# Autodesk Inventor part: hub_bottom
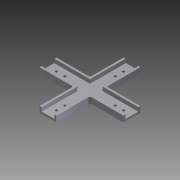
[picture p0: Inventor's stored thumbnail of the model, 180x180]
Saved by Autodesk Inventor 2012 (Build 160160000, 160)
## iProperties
Created: 2011-06
Part Number: hub_bottom
Document SubType Name: Modeling
Designer: Bruce
Density: 1 g/cm^3
Material: Default
Author: Bruce
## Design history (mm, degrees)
sketch "Sketch1"
  geometry: L1 (-50, 50)-(50, 50); L2 (50, 50)-(50, -50); L3 (50, -50)-(-50, -50); L4 (-50, -50)-(-50, 50); L5 (-50, 0)-(50, 0); L6 (0, 50)-(0, -50); L7 (-10, 50)-(-10, 10); L8 (-10, 10)-(-50, 10); L9 (10, 50)-(10, 10); L10 (10, 10)-(50, 10); L11 (50, -10)-(10, -10); L12 (10, -10)-(10, -50); L13 (-10, -50)-(-10, -10); L14 (-10, -10)-(-50, -10); L15 (-10, 50)-(10, 50); L16 (50, 10)-(50, -10); L17 (10, -50)-(-10, -50); L18 (-50, 10)-(-50, -10); 1 further point
  constraints: 36 end point, 8 point on line, 6 perpendicular, 5 parallel, 4 collinear, 4 midpoint, 1 horizontal
  dimensions: "d0" = 50 distance from line of L1 point (0, 0) (= 0.5 x hub_square); "d1" = 50 distance from line of L3 point (0, 0) (= 0.5 x hub_square); "d2" = 50 distance from line of L2 point (0, 0) (= 0.5 x hub_square); "d3" = 50 distance from line of point (0, 0) L4 (= 0.5 x hub_square); "d4" = 10 distance between parallel lines of L6 L7 (= 0.5 x arm_width + structural_cover); "d5" = 10 distance between parallel lines of L6 L9 (= 0.5 x arm_width + structural_cover); "d6" = 10 distance between parallel lines of L5 L8 (= 0.5 x arm_width + structural_cover); "d7" = 10 distance between parallel lines of L14 L5 (= 0.5 x arm_width + structural_cover); "d8" = 10 distance between parallel lines of L6 L13 (= 0.5 x arm_width + structural_cover); "d9" = 10 distance between parallel lines of L12 L6 (= 0.5 x arm_width + structural_cover); "d10" = 10 distance between parallel lines of L11 L5 (= 0.5 x arm_width + structural_cover); "d11" = 10 distance between parallel lines of L10 L5 (= 0.5 x arm_width + structural_cover)
extrude "Extrusion1" new body sketch "Sketch1" distance "d12" = 2.5 (= structural_cover); taper "d13" = 0 deg
sketch "Sketch2"
  geometry: L1 (-10, 50)-(10, 50) reference; L2 (-10, 10)-(-10, 50) reference; L3 (-50, 10)-(-10, 10) reference; L4 (-50, -10)-(-50, 10) reference; L5 (-10, -10)-(-50, -10) reference; L6 (-10, -50)-(-10, -10) reference; L7 (10, -50)-(-10, -50) reference; L8 (10, -10)-(10, -50) reference; L9 (50, -10)-(10, -10) reference; L10 (50, 10)-(50, -10) reference; L11 (10, 10)-(50, 10) reference; L12 (10, 50)-(10, 10) reference; L13 (-7.5, 50)-(-7.5, 7.5); L14 (-7.5, 7.5)-(-50, 7.5); L15 (-50, -7.5)-(-7.5, -7.5); L16 (-7.5, -7.5)-(-7.5, -50); L17 (50, -7.5)-(7.5, -7.5); L18 (7.5, -7.5)-(7.5, -50); L19 (50, 7.5)-(7.5, 7.5); L20 (7.5, 7.5)-(7.5, 50); L21 (-7.5, 50)-(-10, 50); L22 (-10, 10)-(-50, 10); L23 (-50, 7.5)-(-50, 10); L24 (-50, -7.5)-(-50, -10); L25 (-50, -10)-(-10, -10); L26 (-10, -10)-(-10, -50); L27 (-10, -50)-(-7.5, -50); L28 (7.5, -50)-(10, -50); L29 (10, -50)-(10, -10); L30 (10, -10)-(50, -10); L31 (50, -10)-(50, -7.5); L32 (50, 7.5)-(50, 10); L33 (50, 10)-(10, 10); L34 (10, 10)-(10, 50); L35 (10, 50)-(7.5, 50); L36 (-10, 50)-(-10, 10); L37 (-50, 0)-(50, 0); L38 (0, 50)-(0, -50); L39 (-20, 7.5)-(-20, -7.5); L40 (20, 7.5)-(20, -7.5); L41 (-7.5, 20)-(7.5, 20); L42 (-7.5, -20)-(7.5, -20); 1 further point
  constraints: 60 end point, 16 point on line, 13 collinear, 13 perpendicular, 4 midpoint, 2 parallel
  dimensions: "d14" = 2.5 distance between parallel lines of L13 L2 (= structural_cover); "d15" = 2.5 distance between parallel lines of L14 L3 (= structural_cover); "d16" = 2.5 distance between parallel lines of L5 L15 (= structural_cover); "d17" = 2.5 distance between parallel lines of L16 L6 (= structural_cover); "d18" = 2.5 distance between parallel lines of L8 L18 (= structural_cover); "d19" = 2.5 distance between parallel lines of L9 L17 (= structural_cover); "d20" = 2.5 distance between parallel lines of L19 L11 (= structural_cover); "d21" = 2.5 distance between parallel lines of L12 L20 (= structural_cover); "d42" = 30 distance between parallel lines of L4 L39 (= 3 x arm_fixing_spacing); "d43" = 30 distance between parallel lines of L1 L41 (= 3 x arm_fixing_spacing); "d44" = 30 distance between parallel lines of L10 L40 (= 3 x arm_fixing_spacing); "d45" = 30 distance between parallel lines of L7 L42 (= 3 x arm_fixing_spacing)
extrude "Extrusion2" join sketch "Sketch2" distance "d22" = 4.5 (= -0.5 x pinch_gap + 0.5 x arm_height); taper "d23" = 0 deg
sketch "Sketch3"
  geometry: L1 (-10, 50)-(10, 50) reference; L2 (-50, -10)-(-50, 10) reference; L3 (10, -50)-(-10, -50) reference; L4 (50, 10)-(50, -10) reference; L5 (0, 50)-(0, -50); L6 (-50, 0)-(50, 0); C1 r 1.5 at (-40, 0); C2 r 1.5 at (-30, 0); C3 r 1.5 at (0, 40); C4 r 1.5 at (0, 30); C5 r 1.5 at (0, -40); C6 r 1.5 at (0, -30); C7 r 1.5 at (40, 0); C8 r 1.5 at (30, 0); 1 further point
  constraints: 8 centre point, 8 point on line, 4 end point, 4 midpoint
  dimensions: "d24" = 3 diameter of C1 (= arm_bolt_diam); "d25" = 3 diameter of C2 (= arm_bolt_diam); "d26" = 3 diameter of C3 (= arm_bolt_diam); "d27" = 3 diameter of C4 (= arm_bolt_diam); "d28" = 3 diameter of C8 (= arm_bolt_diam); "d29" = 3 diameter of C7 (= arm_bolt_diam); "d30" = 3 diameter of C6 (= arm_bolt_diam); "d31" = 3 diameter of C5 (= arm_bolt_diam); "d32" = 10 distance from line of C1.centre L2 (= arm_fixing_spacing); "d33" = 10 distance of C2.centre C1.centre (= arm_fixing_spacing); "d34" = 10 distance from line of L1 C3.centre (= arm_fixing_spacing); "d35" = 10 distance of C3.centre C4.centre (= arm_fixing_spacing); "d36" = 10 distance from line of L4 C7.centre (= arm_fixing_spacing); "d37" = 10 distance of C7.centre C8.centre (= arm_fixing_spacing); "d38" = 10 distance of C5.centre C6.centre (= arm_fixing_spacing); "d39" = 10 distance from line of C5.centre L3 (= arm_fixing_spacing)
extrude "Extrusion3" cut sketch "Sketch3" distance "d40" = 2.5 (= structural_cover); taper "d41" = 0 deg
fillet "Fillet3" dims "d72" = 2
body "Solid1"
other parameters: "mounting_square" = 45 [user parameter], "arm_width" = 15 [user parameter; used in 8 equation terms], "arm_bolt_diam" = 3 [user parameter; used in 8 equation terms], "structural_cover" = 2.5 [user parameter; used in 18 equation terms], "pinch_gap" = 1 [user parameter; used in 1 equation term], "arm_fixing_spacing" = 10 [user parameter; used in 12 equation terms], "mounting_bolt_diam" = 3 [user parameter]
